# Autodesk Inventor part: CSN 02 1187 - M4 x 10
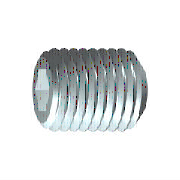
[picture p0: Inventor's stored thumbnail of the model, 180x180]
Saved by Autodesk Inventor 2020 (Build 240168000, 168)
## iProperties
Created: 2019-01
Part Number: CSN 02 1187 - M4 x 10
Material: Ocel, měkká
Description: Stavěcí šroub s vnitřním šestihranem s plochým kuželovým koncem
Document SubType Name: Modeling
Standard: CSN 02 1187
Designer: doma
Standards Organization: CSN
Language: cs-CZ
Size Designation: M4 x 10
Categories: <MemberInstance><Categories><Category DisplayName="Spojovací materiál" InternalName="e4da775c-781d-43d5-af7c-5136215cf5a6" Mnemonic="FSTN"><Category DisplayName
Density: 7.85 g/cm^3
Appearance: Pololeštěná
Mass: 0.882944 g
Surface Area: 1.60311 cm^2
Volume: 0.112477 cm^3
IsCustomPart: 0
Author: doma
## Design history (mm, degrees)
sketch "Náčrt1"
  geometry: L1 (0, 0)-(6.833, 0); L2 (10, 1.155)-(10, 2); L3 (10, 2)-(0, 2); L4 (10, 1.155)-(7.5, 1.155); L5 (7.5, 1.155)-(6.833, 0); L6 (0, -0.4)-(0, 2.4) reference; L7 (0, 2)-(0, 0)
  constraints: 13 end point, 3 parallel, 1 collinear, 1 perpendicular, 1 point on line
  dimensions: "d0" = 2.5 distance of L2.start L4.end (= INTI); "d1" = 60 deg angle of L5 L1; "d2" = 4 diameter of L3 L1 (= NND); "d3" = 2.3094 diameter of L4 L1 (= 1.1547 x SW); "d5" = 10 distance from line of L2 L3.end (= NLG)
revolve "Těleso" sketch "Náčrt1" stored, may be unused: angle "d6" = 90 deg
sketch "Náčrt2"
  geometry: L1 (-0.577, 1)-(0.577, 1); L2 (0.577, 1)-(1.155, 0); L3 (1.155, 0)-(0.577, -1); L4 (0.577, -1)-(-0.577, -1); L5 (-0.577, -1)-(-1.155, 0); L6 (-1.155, 0)-(-0.577, 1); A1 r 1.155 centre (0, 0) between (-0.577, 1) and (0.577, 1) reference; 2 further points
  constraints: 12 end point, 2 point on circle, 1 coincident, 1 horizontal, 11 other
extrude "Drážka" join sketch "Náčrt2" taper "d9" = 0 deg; stored distance "d21" = 10
workaxis "Work Axis1"
workplane "Work Plane1"
body "Solid1"
chamfer "Zkosení1" distance "d7" = 0.42941 (= -0.5 x GD1 + 0.5 x NND); stored, may be unused: angle "d8" = 60 deg (= FAWI), second distance "d29" = 0.42941 (= -0.5 x GD1 + 0.5 x NND)
feature "Závit" dims "d11" = 10 (= NLG), "d12" = 0
chamfer "Zkosení2" distance "d13" = 0.42941 (= -0.5 x GD1 + 0.5 x NND); stored, may be unused: angle "d14" = 60 deg (= FAWI), second distance "d30" = 0.42941 (= -0.5 x GD1 + 0.5 x NND)
other parameters: "NND" = 4 [user parameter; used in 6 equation terms], "NLG" = 10 [user parameter; used in 2 equation terms], "INTI" = 2.5 [user parameter; used in 1 equation term], "FAWI" = 60 deg [user parameter; used in 2 equation terms], "SW" = 2 [user parameter; used in 2 equation terms], "GD1" = 3.14117 (= THREADDIA - 1.2269 x PTC) [user parameter; used in 4 equation terms], "d4" = 0, "FAWI1" = 30 deg [user parameter], "d15" = 0, "d31" = 0, "GUL" = 0.42941 (= 0.61345 x PTC) [user parameter], "SPD" = 3.14117 (= NND - 1.2269 x PTC) [user parameter], "TPU" = 14.28571 (computed from PTC) [user parameter], "TOA" = 30 deg [user parameter], "THREADDIA" = 4 [user parameter; used in 1 equation term], "PTC" = 0.7 [user parameter; used in 5 equation terms], "GAL" = 0.42941 (= 0.61345 x PTC) [user parameter], "E0" = 2.31 (= 1.155 x SW) [user parameter]
